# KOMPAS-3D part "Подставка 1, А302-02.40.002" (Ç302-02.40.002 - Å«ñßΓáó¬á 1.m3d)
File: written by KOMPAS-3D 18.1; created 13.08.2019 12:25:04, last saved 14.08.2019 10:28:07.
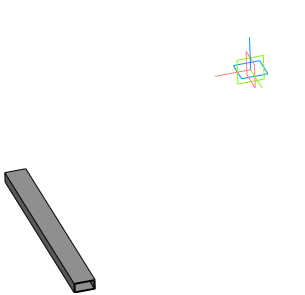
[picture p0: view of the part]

Document properties: Автор: Пользователь Windows; Полное имя файла: D:\Мембранные насосы\Мембранный электропривод\А302-00.00.000 - ASTRA-302 (МЭ200)\3Д ПВХ\А302-02.40.002 - Подставка 1.m3d

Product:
- Part/product: Подставка 1  | designation А302-02.40.002
    Масса: 0.739092
    source file: А302-02.00.000 - ASTRA-302 (МЭ200)\А302-02.40.002 - Подставка.cdw

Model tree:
1. Эскиз:2  (with: Операция выдавливания:1)  (labels: Подставка 1; А302-01.40.000 - Каркас.a3d)
2. Элемент выдавливания:1  (with: Операция выдавливания:1)
     Расстояние 1 = 210; Расстояние 2 = 210

Referenced files in D:\Мембранные насосы\Мембранный электропривод\А302-00.00.000 - ASTRA-302 (МЭ200)\3Д ПВХ\: А302-01.40.000 - Каркас.a3d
